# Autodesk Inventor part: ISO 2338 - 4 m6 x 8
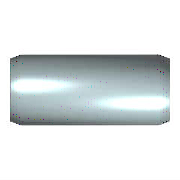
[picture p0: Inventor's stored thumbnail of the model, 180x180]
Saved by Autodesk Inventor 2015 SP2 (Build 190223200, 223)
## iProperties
IsCustomPart: 0
Created: 2012-02
Part Number: ISO 2338 - 4 m6 x 8
Material: Stainless Steel, Austenitic
Description: Parallel Pin
Document SubType Name: Modeling
Standard: ISO 2338
Designer: rYan
Standards Organization: DIN
Language: en-US
Size Designation: 4 m6 x 8
Categories: <MemberInstance><Categories><Category DisplayName="Fasteners" InternalName="e4da775c-781d-43d5-af7c-5136215cf5a6" Mnemonic="FSTN"><Category DisplayName="Pins" I
Density: 8.03 g/cm^3
Appearance: Halbpoliert
Author: rYan
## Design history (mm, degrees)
sketch "Sketch"
  geometry: C1 r 2 at (0, 0); 1 further point
  constraints: 1 centre point, 1 coincident
  dimensions: "d1" = 4 diameter of C1 (= NND)
extrude "Body" new body sketch "Sketch" distance "d2" = 8 (= NLG); taper "d3" = 0 deg
chamfer "Chamfer1" distance "d4" = 0.63 (= PHH); stored, may be unused: angle "d5" = 15 deg (= FAWI), second distance "d11" = 0.63 (= PHH)
chamfer "Chamfer2" distance "d8" = 0.63 (= PHH); stored, may be unused: angle "d9" = 15 deg (= FAWI), second distance "d12" = 0.63 (= PHH)
body "Solid1"
other parameters: "NND" = 4 [user parameter; used in 1 equation term], "NLG" = 8 [user parameter; used in 1 equation term], "PHH" = 0.63 [user parameter; used in 4 equation terms], "FAWI" = 15 deg [user parameter; used in 2 equation terms], "d13" = 0, "d15" = 0, "d16" = 0, "KAH" = 0 [user parameter]
